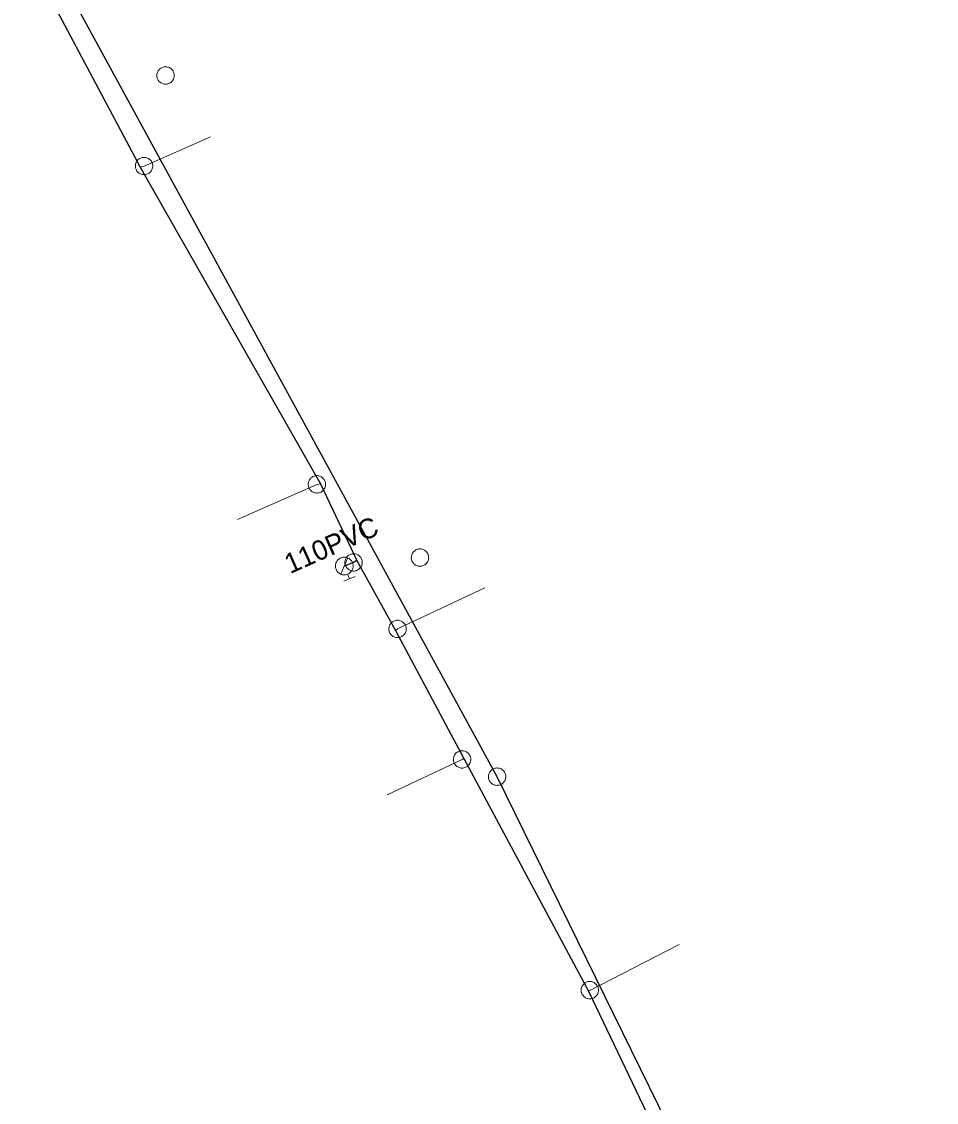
# Model space of a CAD drawing. Extents: x -741806 to -738704, y -1059275 to -1055387.
# Drawn here: x -740597.4 to -740551.4, y -1057520.9 to -1057466.5 of the extents above; entities that cross this region are included whole.
import ezdxf

# ---------------------------------------------------------------- set-up
doc = ezdxf.new("R2010")
doc.units = 0
doc.header["$LTSCALE"] = 0.4
for name, color, linetype, lineweight in [('2', 7, 'Continuous', 25), ('21', 7, 'Continuous', 13), ('3', 7, 'Continuous', 13), ('50', 7, 'Continuous', 13), ('51', 7, 'Continuous', 13), ('52', 7, 'Continuous', 25)]:
    doc.layers.add(name, color=color, linetype=linetype, lineweight=lineweight)
doc.layers.add('53', color=7, linetype='Continuous')

msp = doc.modelspace()

# ---------------------------------------------------------------- linework, layer by layer
at = {"layer": '2'}
msp.add_lwpolyline([(-740551.37, -1057549.6), (-740573.489, -1057504.53), (-740597.07, -1057461.26), (-740629.3, -1057411.95)], dxfattribs=at)
at = {"layer": '21'}
msp.add_line((-740568.886, -1057515.331), (-740564.324, -1057512.979), dxfattribs=at)
for points in [[(-740591.452, -1057473.831), (-740591.26, -1057473.78), (-740587.916, -1057472.311)], [(-740582.381, -1057489.777), (-740582.559, -1057489.81), (-740586.554, -1057491.578)], [(-740578.601, -1057497.165), (-740578.5, -1057497.09), (-740574.105, -1057495.017)], [(-740575.153, -1057503.61), (-740575.25, -1057503.659), (-740579.024, -1057505.45)]]:
    msp.add_lwpolyline(points, dxfattribs=at)
at = {"layer": '3'}
for points in [[(-740590.383, -1057468.832), (-740590.422, -1057468.856), (-740590.458, -1057468.883), (-740590.493, -1057468.914), (-740590.522, -1057468.948), (-740590.549, -1057468.986), (-740590.572, -1057469.026), (-740590.589, -1057469.068), (-740590.603, -1057469.112), (-740590.611, -1057469.157), (-740590.616, -1057469.202), (-740590.615, -1057469.248), (-740590.61, -1057469.294), (-740590.599, -1057469.338), (-740590.585, -1057469.382), (-740590.566, -1057469.423), (-740590.542, -1057469.463), (-740590.514, -1057469.499), (-740590.484, -1057469.533), (-740590.449, -1057469.563), (-740590.411, -1057469.589), (-740590.371, -1057469.611), (-740590.33, -1057469.629), (-740590.286, -1057469.643), (-740590.241, -1057469.652), (-740590.195, -1057469.656), (-740590.149, -1057469.655), (-740590.104, -1057469.65), (-740590.059, -1057469.64), (-740590.016, -1057469.625), (-740589.974, -1057469.605), (-740589.935, -1057469.583), (-740589.899, -1057469.555), (-740589.865, -1057469.524), (-740589.835, -1057469.489), (-740589.809, -1057469.452), (-740589.786, -1057469.412), (-740589.768, -1057469.37), (-740589.754, -1057469.325), (-740589.746, -1057469.281), (-740589.742, -1057469.236), (-740589.742, -1057469.19), (-740589.747, -1057469.144), (-740589.757, -1057469.1), (-740589.772, -1057469.056), (-740589.792, -1057469.015), (-740589.815, -1057468.975), (-740589.842, -1057468.939), (-740589.873, -1057468.905), (-740589.908, -1057468.875), (-740589.946, -1057468.849), (-740589.986, -1057468.827), (-740590.027, -1057468.808), (-740590.072, -1057468.795), (-740590.116, -1057468.786), (-740590.162, -1057468.782), (-740590.208, -1057468.782), (-740590.253, -1057468.788), (-740590.298, -1057468.798), (-740590.341, -1057468.813), (-740590.383, -1057468.831)], [(-740577.578, -1057493.114), (-740577.616, -1057493.139), (-740577.653, -1057493.166), (-740577.686, -1057493.198), (-740577.716, -1057493.232), (-740577.742, -1057493.27), (-740577.764, -1057493.311), (-740577.781, -1057493.353), (-740577.795, -1057493.397), (-740577.802, -1057493.442), (-740577.806, -1057493.487), (-740577.805, -1057493.534), (-740577.799, -1057493.579), (-740577.788, -1057493.623), (-740577.773, -1057493.667), (-740577.753, -1057493.708), (-740577.729, -1057493.747), (-740577.701, -1057493.783), (-740577.67, -1057493.817), (-740577.635, -1057493.846), (-740577.596, -1057493.872), (-740577.556, -1057493.894), (-740577.515, -1057493.911), (-740577.47, -1057493.924), (-740577.426, -1057493.933), (-740577.379, -1057493.936), (-740577.334, -1057493.934), (-740577.289, -1057493.929), (-740577.244, -1057493.918), (-740577.201, -1057493.903), (-740577.159, -1057493.883), (-740577.121, -1057493.859), (-740577.085, -1057493.832), (-740577.051, -1057493.8), (-740577.021, -1057493.764), (-740576.996, -1057493.728), (-740576.973, -1057493.687), (-740576.956, -1057493.645), (-740576.943, -1057493.6), (-740576.935, -1057493.556), (-740576.931, -1057493.511), (-740576.933, -1057493.465), (-740576.938, -1057493.419), (-740576.949, -1057493.374), (-740576.964, -1057493.331), (-740576.984, -1057493.29), (-740577.008, -1057493.251), (-740577.036, -1057493.214), (-740577.067, -1057493.181), (-740577.103, -1057493.152), (-740577.141, -1057493.126), (-740577.181, -1057493.104), (-740577.223, -1057493.086), (-740577.267, -1057493.074), (-740577.312, -1057493.065), (-740577.358, -1057493.062), (-740577.404, -1057493.063), (-740577.448, -1057493.069), (-740577.494, -1057493.08), (-740577.536, -1057493.095), (-740577.577, -1057493.114)], [(-740573.681, -1057504.136), (-740573.72, -1057504.159), (-740573.757, -1057504.185), (-740573.793, -1057504.215), (-740573.823, -1057504.248), (-740573.851, -1057504.285), (-740573.875, -1057504.325), (-740573.893, -1057504.366), (-740573.909, -1057504.409), (-740573.918, -1057504.454), (-740573.924, -1057504.499), (-740573.925, -1057504.545), (-740573.921, -1057504.591), (-740573.911, -1057504.636), (-740573.899, -1057504.68), (-740573.88, -1057504.722), (-740573.858, -1057504.762), (-740573.831, -1057504.799), (-740573.802, -1057504.834), (-740573.768, -1057504.865), (-740573.731, -1057504.892), (-740573.692, -1057504.916), (-740573.651, -1057504.935), (-740573.607, -1057504.95), (-740573.563, -1057504.96), (-740573.517, -1057504.966), (-740573.471, -1057504.965), (-740573.426, -1057504.962), (-740573.38, -1057504.953), (-740573.337, -1057504.94), (-740573.295, -1057504.921), (-740573.255, -1057504.9), (-740573.218, -1057504.873), (-740573.183, -1057504.843), (-740573.152, -1057504.809), (-740573.124, -1057504.773), (-740573.1, -1057504.733), (-740573.082, -1057504.692), (-740573.067, -1057504.648), (-740573.057, -1057504.604), (-740573.051, -1057504.559), (-740573.051, -1057504.513), (-740573.054, -1057504.467), (-740573.063, -1057504.422), (-740573.076, -1057504.378), (-740573.095, -1057504.336), (-740573.117, -1057504.296), (-740573.143, -1057504.259), (-740573.173, -1057504.224), (-740573.207, -1057504.193), (-740573.244, -1057504.166), (-740573.283, -1057504.143), (-740573.324, -1057504.123), (-740573.368, -1057504.108), (-740573.412, -1057504.098), (-740573.458, -1057504.093), (-740573.504, -1057504.092), (-740573.549, -1057504.096), (-740573.595, -1057504.105), (-740573.638, -1057504.119), (-740573.68, -1057504.136)]]:
    msp.add_lwpolyline(points, dxfattribs=at)
at = {"layer": '50'}
for p, q in [((-740581.181, -1057493.924), (-740581.006, -1057493.512)), ((-740581.181, -1057493.924), (-740581.356, -1057494.332)), ((-740581.013, -1057494.338), (-740580.919, -1057494.571)), ((-740581.203, -1057494.686), (-740580.919, -1057494.571)), ((-740580.633, -1057494.456), (-740580.919, -1057494.571))]:
    msp.add_line(p, q, dxfattribs=at)
msp.add_lwpolyline([(-740581.594, -1057494.087), (-740581.573, -1057494.131), (-740581.551, -1057494.172), (-740581.522, -1057494.21), (-740581.49, -1057494.243), (-740581.458, -1057494.273), (-740581.417, -1057494.301), (-740581.377, -1057494.323), (-740581.333, -1057494.343), (-740581.29, -1057494.358), (-740581.244, -1057494.365), (-740581.197, -1057494.37), (-740581.15, -1057494.371), (-740581.104, -1057494.363), (-740581.058, -1057494.354), (-740581.015, -1057494.339), (-740580.973, -1057494.319), (-740580.933, -1057494.298), (-740580.895, -1057494.268), (-740580.861, -1057494.236), (-740580.829, -1057494.2), (-740580.803, -1057494.163), (-740580.78, -1057494.122), (-740580.762, -1057494.079), (-740580.748, -1057494.036), (-740580.738, -1057493.989), (-740580.733, -1057493.943), (-740580.734, -1057493.897), (-740580.738, -1057493.849), (-740580.751, -1057493.804), (-740580.762, -1057493.759), (-740580.783, -1057493.716), (-740580.808, -1057493.676), (-740580.834, -1057493.641), (-740580.866, -1057493.604), (-740580.902, -1057493.574), (-740580.939, -1057493.546), (-740580.98, -1057493.525), (-740581.023, -1057493.504), (-740581.069, -1057493.491), (-740581.114, -1057493.483), (-740581.162, -1057493.479), (-740581.208, -1057493.48), (-740581.253, -1057493.483), (-740581.301, -1057493.494), (-740581.345, -1057493.508), (-740581.387, -1057493.528), (-740581.426, -1057493.553), (-740581.465, -1057493.581), (-740581.499, -1057493.611), (-740581.53, -1057493.648), (-740581.556, -1057493.684), (-740581.58, -1057493.727), (-740581.598, -1057493.768), (-740581.613, -1057493.812), (-740581.62, -1057493.859), (-740581.627, -1057493.905), (-740581.626, -1057493.952), (-740581.619, -1057493.998), (-740581.609, -1057494.043)], close=True, dxfattribs=at)
at = {"layer": '51'}
for points in [[(-740591.044, -1057474.16), (-740591.006, -1057474.136), (-740590.97, -1057474.107), (-740590.937, -1057474.075), (-740590.908, -1057474.04), (-740590.883, -1057474.001), (-740590.862, -1057473.96), (-740590.845, -1057473.918), (-740590.833, -1057473.874), (-740590.826, -1057473.829), (-740590.823, -1057473.783), (-740590.825, -1057473.737), (-740590.832, -1057473.691), (-740590.843, -1057473.647), (-740590.859, -1057473.605), (-740590.88, -1057473.564), (-740590.905, -1057473.525), (-740590.933, -1057473.489), (-740590.965, -1057473.457), (-740591.001, -1057473.428), (-740591.04, -1057473.403), (-740591.08, -1057473.382), (-740591.122, -1057473.364), (-740591.167, -1057473.353), (-740591.212, -1057473.345), (-740591.258, -1057473.343), (-740591.304, -1057473.345), (-740591.348, -1057473.351), (-740591.393, -1057473.363), (-740591.436, -1057473.379), (-740591.477, -1057473.4), (-740591.515, -1057473.424), (-740591.551, -1057473.453), (-740591.584, -1057473.485), (-740591.612, -1057473.52), (-740591.638, -1057473.559), (-740591.659, -1057473.6), (-740591.675, -1057473.642), (-740591.688, -1057473.686), (-740591.695, -1057473.731), (-740591.698, -1057473.777), (-740591.696, -1057473.823), (-740591.689, -1057473.869), (-740591.677, -1057473.912), (-740591.662, -1057473.955), (-740591.641, -1057473.996), (-740591.616, -1057474.035), (-740591.587, -1057474.07), (-740591.556, -1057474.103), (-740591.52, -1057474.132), (-740591.481, -1057474.157), (-740591.441, -1057474.178), (-740591.398, -1057474.196), (-740591.354, -1057474.207), (-740591.309, -1057474.215), (-740591.263, -1057474.217), (-740591.217, -1057474.215), (-740591.172, -1057474.209), (-740591.127, -1057474.197), (-740591.085, -1057474.181), (-740591.045, -1057474.16)], [(-740582.989, -1057489.886), (-740582.979, -1057489.93), (-740582.964, -1057489.973), (-740582.944, -1057490.015), (-740582.921, -1057490.054), (-740582.893, -1057490.091), (-740582.862, -1057490.125), (-740582.827, -1057490.154), (-740582.789, -1057490.181), (-740582.749, -1057490.202), (-740582.707, -1057490.22), (-740582.663, -1057490.233), (-740582.618, -1057490.242), (-740582.572, -1057490.246), (-740582.527, -1057490.245), (-740582.481, -1057490.239), (-740582.436, -1057490.229), (-740582.393, -1057490.214), (-740582.352, -1057490.195), (-740582.313, -1057490.17), (-740582.276, -1057490.142), (-740582.243, -1057490.111), (-740582.213, -1057490.077), (-740582.187, -1057490.039), (-740582.165, -1057489.999), (-740582.147, -1057489.957), (-740582.134, -1057489.912), (-740582.125, -1057489.868), (-740582.121, -1057489.822), (-740582.122, -1057489.776), (-740582.128, -1057489.731), (-740582.139, -1057489.687), (-740582.153, -1057489.644), (-740582.173, -1057489.602), (-740582.196, -1057489.563), (-740582.224, -1057489.526), (-740582.256, -1057489.492), (-740582.291, -1057489.463), (-740582.328, -1057489.436), (-740582.368, -1057489.415), (-740582.41, -1057489.397), (-740582.454, -1057489.384), (-740582.5, -1057489.375), (-740582.545, -1057489.372), (-740582.59, -1057489.372), (-740582.636, -1057489.378), (-740582.681, -1057489.388), (-740582.724, -1057489.404), (-740582.765, -1057489.422), (-740582.805, -1057489.447), (-740582.841, -1057489.475), (-740582.874, -1057489.506), (-740582.905, -1057489.54), (-740582.93, -1057489.578), (-740582.953, -1057489.618), (-740582.97, -1057489.661), (-740582.984, -1057489.705), (-740582.992, -1057489.749), (-740582.996, -1057489.795), (-740582.995, -1057489.841), (-740582.989, -1057489.885)], [(-740581.092, -1057493.95), (-740581.069, -1057493.989), (-740581.041, -1057494.025), (-740581.009, -1057494.058), (-740580.974, -1057494.087), (-740580.936, -1057494.113), (-740580.895, -1057494.135), (-740580.853, -1057494.152), (-740580.809, -1057494.165), (-740580.764, -1057494.172), (-740580.719, -1057494.176), (-740580.672, -1057494.174), (-740580.627, -1057494.168), (-740580.582, -1057494.158), (-740580.54, -1057494.142), (-740580.498, -1057494.122), (-740580.459, -1057494.098), (-740580.423, -1057494.07), (-740580.39, -1057494.038), (-740580.361, -1057494.002), (-740580.335, -1057493.964), (-740580.314, -1057493.924), (-740580.296, -1057493.882), (-740580.284, -1057493.837), (-740580.276, -1057493.793), (-740580.273, -1057493.746), (-740580.274, -1057493.7), (-740580.28, -1057493.656), (-740580.292, -1057493.611), (-740580.307, -1057493.568), (-740580.327, -1057493.526), (-740580.351, -1057493.488), (-740580.379, -1057493.452), (-740580.411, -1057493.419), (-740580.446, -1057493.39), (-740580.484, -1057493.364), (-740580.525, -1057493.342), (-740580.567, -1057493.325), (-740580.611, -1057493.312), (-740580.656, -1057493.305), (-740580.701, -1057493.301), (-740580.747, -1057493.303), (-740580.793, -1057493.309), (-740580.837, -1057493.32), (-740580.88, -1057493.335), (-740580.922, -1057493.356), (-740580.961, -1057493.38), (-740580.996, -1057493.409), (-740581.03, -1057493.439), (-740581.059, -1057493.475), (-740581.085, -1057493.513), (-740581.106, -1057493.554), (-740581.124, -1057493.596), (-740581.136, -1057493.64), (-740581.144, -1057493.685), (-740581.147, -1057493.731), (-740581.146, -1057493.777), (-740581.14, -1057493.821), (-740581.128, -1057493.866), (-740581.113, -1057493.909), (-740581.093, -1057493.95)], [(-740578.063, -1057497.09), (-740578.065, -1057497.045), (-740578.072, -1057497), (-740578.084, -1057496.955), (-740578.1, -1057496.913), (-740578.121, -1057496.872), (-740578.146, -1057496.833), (-740578.175, -1057496.798), (-740578.207, -1057496.765), (-740578.243, -1057496.737), (-740578.281, -1057496.712), (-740578.322, -1057496.691), (-740578.365, -1057496.674), (-740578.409, -1057496.662), (-740578.454, -1057496.655), (-740578.5, -1057496.653), (-740578.546, -1057496.655), (-740578.591, -1057496.662), (-740578.635, -1057496.674), (-740578.678, -1057496.691), (-740578.719, -1057496.712), (-740578.757, -1057496.737), (-740578.793, -1057496.765), (-740578.825, -1057496.798), (-740578.854, -1057496.833), (-740578.879, -1057496.872), (-740578.9, -1057496.913), (-740578.916, -1057496.955), (-740578.928, -1057497), (-740578.935, -1057497.045), (-740578.938, -1057497.091), (-740578.935, -1057497.136), (-740578.928, -1057497.181), (-740578.916, -1057497.226), (-740578.9, -1057497.268), (-740578.879, -1057497.309), (-740578.854, -1057497.348), (-740578.825, -1057497.383), (-740578.793, -1057497.416), (-740578.757, -1057497.444), (-740578.719, -1057497.469), (-740578.678, -1057497.49), (-740578.635, -1057497.507), (-740578.591, -1057497.518), (-740578.546, -1057497.526), (-740578.5, -1057497.528), (-740578.454, -1057497.526), (-740578.409, -1057497.518), (-740578.365, -1057497.507), (-740578.322, -1057497.49), (-740578.281, -1057497.469), (-740578.243, -1057497.444), (-740578.207, -1057497.416), (-740578.175, -1057497.383), (-740578.146, -1057497.348), (-740578.121, -1057497.309), (-740578.1, -1057497.268), (-740578.084, -1057497.226), (-740578.072, -1057497.181), (-740578.065, -1057497.136), (-740578.063, -1057497.091)], [(-740574.813, -1057503.659), (-740574.815, -1057503.614), (-740574.822, -1057503.569), (-740574.834, -1057503.524), (-740574.85, -1057503.482), (-740574.871, -1057503.441), (-740574.896, -1057503.402), (-740574.925, -1057503.367), (-740574.957, -1057503.334), (-740574.993, -1057503.306), (-740575.031, -1057503.281), (-740575.072, -1057503.26), (-740575.115, -1057503.243), (-740575.159, -1057503.231), (-740575.204, -1057503.224), (-740575.25, -1057503.222), (-740575.296, -1057503.224), (-740575.341, -1057503.231), (-740575.385, -1057503.243), (-740575.428, -1057503.26), (-740575.469, -1057503.281), (-740575.507, -1057503.306), (-740575.543, -1057503.334), (-740575.575, -1057503.367), (-740575.604, -1057503.402), (-740575.629, -1057503.441), (-740575.65, -1057503.482), (-740575.666, -1057503.524), (-740575.678, -1057503.569), (-740575.685, -1057503.614), (-740575.688, -1057503.66), (-740575.685, -1057503.705), (-740575.678, -1057503.75), (-740575.666, -1057503.795), (-740575.65, -1057503.837), (-740575.629, -1057503.878), (-740575.604, -1057503.917), (-740575.575, -1057503.952), (-740575.543, -1057503.985), (-740575.507, -1057504.013), (-740575.469, -1057504.038), (-740575.428, -1057504.059), (-740575.385, -1057504.076), (-740575.341, -1057504.087), (-740575.296, -1057504.095), (-740575.25, -1057504.097), (-740575.204, -1057504.095), (-740575.159, -1057504.087), (-740575.115, -1057504.076), (-740575.072, -1057504.059), (-740575.031, -1057504.038), (-740574.993, -1057504.013), (-740574.957, -1057503.985), (-740574.925, -1057503.952), (-740574.896, -1057503.917), (-740574.871, -1057503.878), (-740574.85, -1057503.837), (-740574.834, -1057503.795), (-740574.822, -1057503.75), (-740574.815, -1057503.705), (-740574.813, -1057503.66)], [(-740568.382, -1057515.28), (-740568.384, -1057515.235), (-740568.392, -1057515.19), (-740568.404, -1057515.145), (-740568.419, -1057515.103), (-740568.441, -1057515.062), (-740568.465, -1057515.023), (-740568.495, -1057514.988), (-740568.527, -1057514.955), (-740568.563, -1057514.927), (-740568.6, -1057514.902), (-740568.642, -1057514.881), (-740568.684, -1057514.864), (-740568.728, -1057514.852), (-740568.774, -1057514.845), (-740568.82, -1057514.843), (-740568.865, -1057514.845), (-740568.911, -1057514.852), (-740568.955, -1057514.864), (-740568.997, -1057514.881), (-740569.039, -1057514.902), (-740569.076, -1057514.927), (-740569.112, -1057514.955), (-740569.144, -1057514.988), (-740569.174, -1057515.023), (-740569.198, -1057515.062), (-740569.22, -1057515.103), (-740569.235, -1057515.145), (-740569.247, -1057515.19), (-740569.255, -1057515.235), (-740569.257, -1057515.281), (-740569.255, -1057515.326), (-740569.247, -1057515.371), (-740569.235, -1057515.416), (-740569.22, -1057515.458), (-740569.198, -1057515.499), (-740569.174, -1057515.538), (-740569.144, -1057515.573), (-740569.112, -1057515.606), (-740569.076, -1057515.634), (-740569.039, -1057515.659), (-740568.997, -1057515.68), (-740568.955, -1057515.697), (-740568.911, -1057515.708), (-740568.865, -1057515.716), (-740568.82, -1057515.718), (-740568.774, -1057515.716), (-740568.728, -1057515.708), (-740568.684, -1057515.697), (-740568.642, -1057515.68), (-740568.6, -1057515.659), (-740568.563, -1057515.634), (-740568.527, -1057515.606), (-740568.495, -1057515.573), (-740568.465, -1057515.538), (-740568.441, -1057515.499), (-740568.419, -1057515.458), (-740568.404, -1057515.416), (-740568.392, -1057515.371), (-740568.384, -1057515.326), (-740568.382, -1057515.281)]]:
    msp.add_lwpolyline(points, dxfattribs=at)
at = {"layer": '52'}
for points in [[(-740629.568, -1057413.446), (-740618.379, -1057430.067), (-740601.454, -1057456.58), (-740598.046, -1057461.412), (-740591.452, -1057473.831), (-740582.381, -1057489.777), (-740580.548, -1057493.651), (-740578.601, -1057497.165), (-740575.153, -1057503.61), (-740568.886, -1057515.331), (-740551.89, -1057550.899), (-740551.756, -1057567.162), (-740551.934, -1057571.904)], [(-740580.548, -1057493.651), (-740580.71, -1057493.74), (-740581.18, -1057493.929)]]:
    msp.add_lwpolyline(points, dxfattribs=at)

# ---------------------------------------------------------------- texts
at = {"layer": '53'}
msp.add_text('110PVC', height=1, rotation=24, dxfattribs=at).set_placement((-740583.905, -1057494.33))

doc.saveas('drawing.dxf')
